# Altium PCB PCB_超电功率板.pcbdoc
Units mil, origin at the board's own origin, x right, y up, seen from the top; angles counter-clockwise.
Board outline 3510 x 2835 mil, 2 copper layers (Top Layer, Bottom Layer); 57 components, 25 nets, 167 pads, 0 vias.
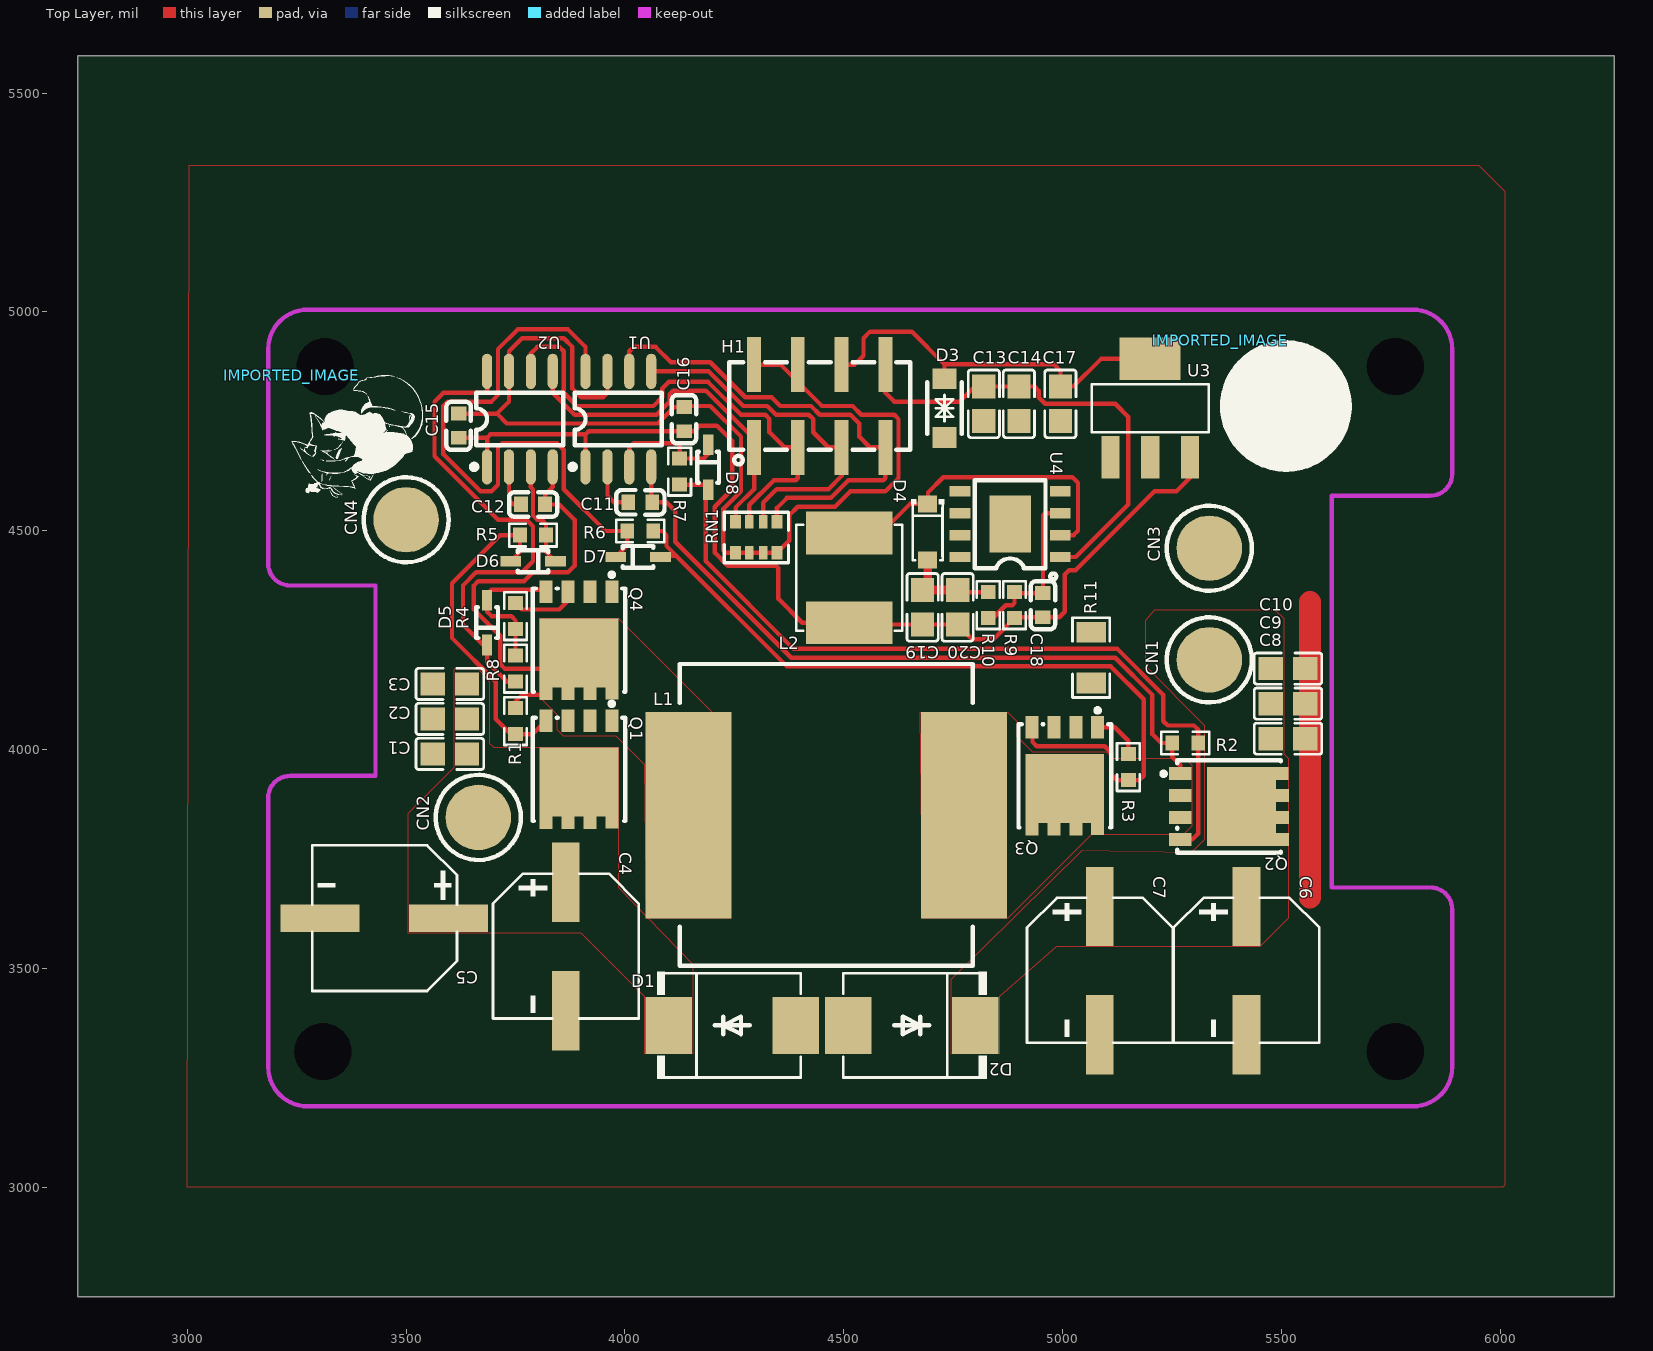
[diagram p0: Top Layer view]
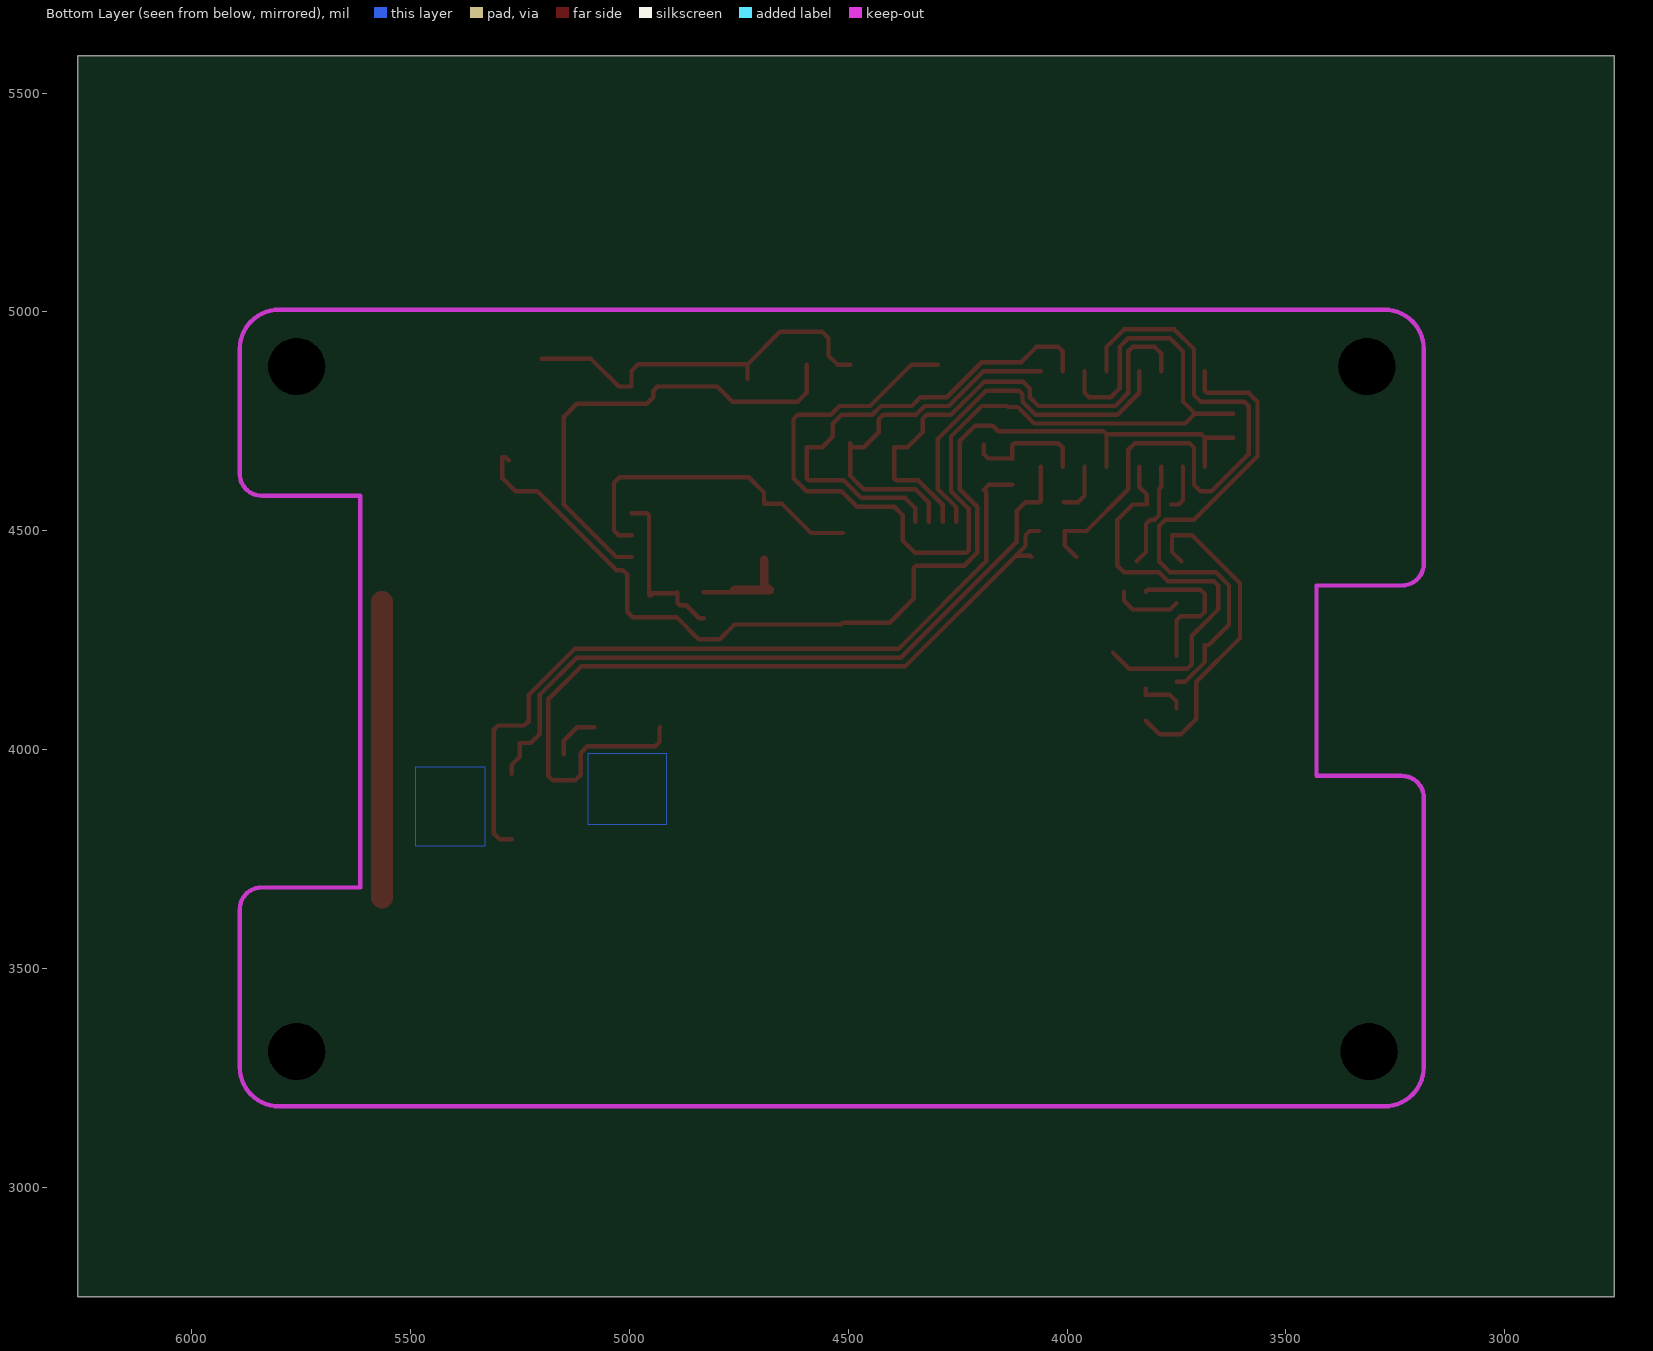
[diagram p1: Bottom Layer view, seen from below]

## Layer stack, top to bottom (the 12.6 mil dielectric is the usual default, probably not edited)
Top Layer: signal copper (thickness not stored)
Dielectric: dielectric 12.6, FR-4, Dk 4.8
Bottom Layer: signal copper (thickness not stored)

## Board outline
6260,2750 2750,2750 2750,5585 6260,5585
cut-out: 3380,4875 ccw(c3315,4875) 3250,4875 ccw(c3315,4875)
cut-out: 3375,3310 ccw(c3310,3310) 3245,3310 ccw(c3310,3310)
cut-out: 5825,3310 ccw(c5760,3310) 5695,3310 ccw(c5760,3310)
cut-out: 5825,4875 ccw(c5760,4875) 5695,4875 ccw(c5760,4875)

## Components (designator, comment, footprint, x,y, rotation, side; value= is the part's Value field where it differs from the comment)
C1 "22u" C0805 3600,3990 r180 top
C2 "22u" C0805 3600,4070 r180 top
C3 "22u" C0805 3600,4150 r180 top
C4 "220uF" CAP-SMD_BD8.0-L8.3-W8.3-LS9.3-FD 3865,3550 r270 top
C5 "220uF" CAP-SMD_BD8.0-L8.3-W8.3-LS9.3-FD 3450,3615 r180 top
C6 "220uF" CAP-SMD_BD8.0-L8.3-W8.3-LS9.3-FD 5420,3495 r270 top
C7 "220uF" CAP-SMD_BD8.0-L8.3-W8.3-LS9.3-FD 5085,3495 r270 top
C8 "22u" C0805 5515,4025 r0 top
C9 "22u" C0805 5515,4105 r0 top
C10 "22u" C0805 5515,4185 r0 top
C11 "100n" C0603 4035,4565 r180 top
C12 "100n" C0603 3790,4560 r180 top
C13 "22u" C0805 4820,4790 r270 top
C14 "22u" C0805 4900,4790 r270 top
C15 "1u" C0603 3620,4740 r90 top
C16 "1u" C0603 4135,4755 r90 top
C17 "22u" C0805 4995,4790 r270 top
C18 "330pF" C0603 4955,4330 r90 top
C19 "22u" C0805 4680,4325 r90 top
C20 "22u" C0805 4760,4325 r90 top
CN1 "m3铜柱" SMT铜柱 5335,4205 r0 top
CN2 "m3铜柱" SMT铜柱 3665.01,3845 r0 top
CN3 "m3铜柱" SMT铜柱 5335,4460 r0 top
CN4 "m3铜柱" SMT铜柱 3500.01,4525 r0 top
D1 "5.0SMDJ30A" SMC_L6.9-W5.9-LS7.9-RD 4245,3370 r0 top
D2 "5.0SMDJ30A" SMC_L6.9-W5.9-LS7.9-RD 4655,3370 r180 top
D3 "SMFJ5.0CA" SOD-123FL_L2.8-W1.8-LS3.7-BI 4730,4780 r90 top
D4 "DSK310_C713648" SOD-123_L2.7-W1.8-LS3.7-RD 4691.5,4497.2 r270 top
D5 "1N4007WS" SOD-323_L1.6-W1.3-LS2.6-RD 3685,4290 r90 top
D6 "1N4007WS" SOD-323_L1.6-W1.3-LS2.6-RD 3790,4430 r180 top
D7 "1N4007WS" SOD-323_L1.6-W1.3-LS2.6-RD 4030,4440 r0 top
D8 "1N4007WS" SOD-323_L1.6-W1.3-LS2.6-RD 4190,4645 r270 top
H1 "MF254VS-12-08P" HDR-SMD_8P-P2.54_MF254VS-12-08P 4445,4785 r0 top
IMPORTED_IMAGE "IMPORTED_IMAGE" IMPORTED_IMAGE 3238.58,4855.24 r0 top
IMPORTED_IMAGE "IMPORTED_IMAGE" IMPORTED_IMAGE 5360.03,4934.98 r0 top
L1 "15uH" IND-SMD_L17.5-W17.0_YXMAC1770 4460,3850 r0 top
L2 "330uH" IND-SMD_L6.0-W6.0_SWPA6045S 4512.2,4392.2 r90 top
Q1 "BSC070N10NS5" PG-TDSON-8_L5.0-W6.0-P1.27-BL-EP 3895.03,3954.97 r180 top
Q2 "BSC070N10NS5" PG-TDSON-8_L5.0-W6.0-P1.27-BL-EP 5380.03,3869.97 r270 top
Q3 "BSC070N10NS5" PG-TDSON-8_L5.0-W6.0-P1.27-BL-EP 5005.03,3939.97 r180 top
Q4 "BSC070N10NS5" PG-TDSON-8_L5.0-W6.0-P1.27-BL-EP 3895.03,4249.97 r180 top
R1 "10k" R0603 3750,4065 r90 top
R2 "10k" R0603 5280,4015 r180 top
R3 "10k" R0603 5150,3960 r90 top
R4 "10k" R0603 3750,4305 r270 top
R5 "4.7" R0603 3790,4490 r180 top
R6 "4.7" R0603 4035,4499.3 r0 top
R7 "4.7" R0603 4125,4635 r270 top
R8 "4.7" R0603 3750,4185 r90 top
R9 "33k" R0603 4890,4330 r90 top
R10 "4.7k" R0603 4830,4330 r90 top
R11 "0" R1206 5065,4210 r90 top
RN1 "10k" RES-ARRAY-SMD_0603-8P-L3.2-W1.6-BL 4300,4485 r180 top
U1 "UCC27211D" SOIC-8_L4.9-W3.9-P1.27-LS6.2-BL 3984.97,4754.99 r0 top
U2 "UCC27211D" SOIC-8_L4.9-W3.9-P1.27-LS6.2-BL 3759.97,4754.99 r0 top
U3 "AMS1117-5.0" SOT-223_L6.5-W3.5-P2.30-LS7.0-BR 5200,4780 r270 top
U4 "XL7005ADJ" ESOP-8_L4.9-W3.9-P1.27-LS6.0-BL-EP 4880,4515 r90 top

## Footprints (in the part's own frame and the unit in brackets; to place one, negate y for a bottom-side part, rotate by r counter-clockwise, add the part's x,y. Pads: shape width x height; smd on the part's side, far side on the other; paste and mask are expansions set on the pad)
C0603 [mm]
  rect 0.8x0.9 smd paste+0 mask+0.051: 1(-0.7,0) 2(0.7,0)
  silkscreen extent -1.41,-0.71 1.39,0.72
C0805 [mm]
  rect 1.41x1.35 smd paste-100 mask+0.051: 1(-1,0) 2(1,0)
  silkscreen extent -1.96,-0.9 1.96,0.9
CAP-SMD_BD8.0-L8.3-W8.3-LS9.3-FD [mm]
  rect 4.6x1.6 smd paste+0 mask+0.051: 1(-3.724,0) 2(3.724,0)
  silkscreen extent -4.23,-4.23 4.18,4.23
ESOP-8_L4.9-W3.9-P1.27-LS6.0-BL-EP [mm]
  rect 0.6x1.2 smd paste+0 mask+0.051: 1(-1.905,-2.908) 2(-0.635,-2.908) 3(0.635,-2.908) 4(1.905,-2.908) 5(1.905,2.908) 6(0.635,2.908) 7(-0.635,2.908) 8(-1.905,2.908)
  rect 3.3x2.4 smd paste+0 mask+0.051: 9(0,0)
  silkscreen extent -3.2,-2.67 2.55,2.05
HDR-SMD_8P-P2.54_MF254VS-12-08P [mm]
  rect 0.8x3.2 smd paste+0 mask+0.051: 1(-3.81,-2.4) 2(-3.81,2.4) 3(-1.27,-2.4) 4(-1.27,2.4) 5(1.27,-2.4) 6(1.27,2.4) 7(3.81,-2.4) 8(3.81,2.4)
  silkscreen extent -5.25,-3.39 5.25,2.54
IMPORTED_IMAGE [mil]
  silkscreen extent 0,-280 300,0
IND-SMD_L6.0-W6.0_SWPA6045S [mm]
  rect 2.474x5.02 smd paste+0 mask+0.051: 1(-2.603,0) 2(2.603,0)
  silkscreen extent -3.08,-3.08 3.08,3.08
IND-SMD_L17.5-W17.0_YXMAC1770 [mm]
  rect 5x12 smd paste+0 mask+0.051: 1(-8,0) 2(8,0)
  silkscreen extent -8.5,-8.73 8.5,8.78
PG-TDSON-8_L5.0-W6.0-P1.27-BL-EP [mil]
  rect 29.5x51.2 smd paste-3937.01 mask+2: 1(-75,-111) 2(-25,-111) 3(25,-111) 4(75,-111) 5(75,111) 6(25,111) 7(-25,111) 8(-75,110)
  rect 179.53x157.48 smd paste-3937.01 mask+2: 9(0,29)
  silkscreen extent -106,-154 106,118
R0603 [mil]
  rect 31.75x34.02 smd paste-3937.01 mask+2: 1(-29.66,0) 2(29.66,0)
  silkscreen extent -55,-26 55,26
R1206 [mil]
  rect 47.54x66.97 smd paste-3937.01 mask+2: 1(-58.22,0) 2(58.22,0)
  silkscreen extent -91,-42 91,42
RES-ARRAY-SMD_0603-8P-L3.2-W1.6-BL [mm]
  rect 0.65x0.8 smd paste+0 mask+0.051: 1(-1.2,-0.9) 4(1.2,-0.9) 5(1.2,0.9) 8(-1.2,0.9)
  rect 0.5x0.8 smd paste+0 mask+0.051: 2(-0.4,-0.9) 3(0.4,-0.9) 6(0.4,0.9) 7(-0.4,0.9)
  silkscreen extent -1.87,-1.45 1.87,1.47
SMC_L6.9-W5.9-LS7.9-RD [mm]
  rect 2.7x3.3 smd paste+0 mask+0.051: 1(-3.686,0) 2(3.686,0)
  silkscreen extent -4.36,-3.1 3.98,3.1
SMT铜柱 [mm]
  round 3.8 smd paste+0 mask+0.051: 1(0,0)
  silkscreen extent -2.47,-2.47 2.47,2.47
SOD-123_L2.7-W1.8-LS3.7-RD [mm]
  rect 1x1.1 smd paste+0 mask+0.051: 1(-1.627,0) 2(1.627,0)
  silkscreen extent -1.9,-0.94 1.65,0.95
SOD-123FL_L2.8-W1.8-LS3.7-BI [mm]
  rect 1.2x1.4 smd paste+0 mask+0.051: 1(-1.7,0) 2(1.7,0)
  silkscreen extent -1.5,-1 1.5,1
SOD-323_L1.6-W1.3-LS2.6-RD [mm]
  rect 1.2x0.6 smd paste+0 mask+0.05: 1(-1.3,0) 2(1.3,0)
  silkscreen extent -0.89,-0.64 0.89,0.64
SOIC-8_L4.9-W3.9-P1.27-LS6.2-BL [mm]
  oval 0.588x2.045 smd paste+0 mask+0.051: 1(-1.905,-2.772) 2(-0.635,-2.772) 3(0.635,-2.772) 4(1.905,-2.772) 5(1.905,2.772) 6(0.635,2.772) 7(-0.635,2.772) 8(-1.905,2.772)
  silkscreen extent -2.8,-2.92 2.53,1.52
SOT-223_L6.5-W3.5-P2.30-LS7.0-BR [mm]
  rect 2.465x1.05 smd paste+0 mask+0.051: 1(2.858,-2.3) 2(2.857,0) 3(2.857,2.3)
  rect 2.465x3.54 smd paste+0 mask+0.051: 4(-2.857,0)
  silkscreen extent -1.4,-3.4 1.4,3.4

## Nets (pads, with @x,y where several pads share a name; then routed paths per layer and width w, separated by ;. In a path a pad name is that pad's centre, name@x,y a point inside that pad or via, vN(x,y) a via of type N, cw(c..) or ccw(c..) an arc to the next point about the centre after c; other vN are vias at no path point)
10V: C15.1 C16.1 C18.1 C19.1 C20.1 L2.1 R9.1 U1.1 U2.1 U3.3 | length 2538.7
  Top Layer w10: C15.1 3685,4712.4 ; U2.1 3685,4712.4 ; U1.1 3910,4719.6 3910,4720 ; L2.1 4516.3,4285.63 C19.1 C20.1 4793.43,4252.2 4841.85,4252.2 R9.1 4892.09,4302.44 C18.1 ; L2.1@4512.2,4290 4405,4290 4350,4345 4350,4415 4345,4420 4235,4420 4205,4450 4205,4555 4245,4595 4245,4705 4210,4740 4170,4740 4157.4,4727.4 C16.1 3917.4,4727.4 3910,4720 ; C18.1 4992.4,4302.4 5005,4315 5005,4400 5015,4410 5030,4410 5210,4590 5260,4590 5290.55,4620.55 U3.3 5282.5,4667.5 U3.3@5275.6,4660.6 ; 3685,4712.4 3692.6,4720 3910,4720
$1N34: D5.2 Q4.4 R4.2 R8.2 | length 334.4
  Top Layer w10: R8.2 R4.2 ; R4.2 3750,4295 3740,4305 3695,4305 3685,4315 D5.2 3685,4355 3695,4365 3816,4365 Q4.4
$1N35: D6.2 Q1.4 R1.1 R5.2 | length 763.3
  Top Layer w10: D6.2 3760.34,4451.52 R5.2 ; R1.1 3739.7,4035.3 3705,4070 3705,4155 3605,4255 3605,4380 3715,4490 R5.2 ; R1.1 3789.34,4035.34 Q1.4
$1N36: D8.2 Q2.4 R2.1 R7.2 | length 1838.1
  Top Layer w10: R7.2 4178.48,4605.34 D8.2 4185,4588.8 4185,4430 4385,4230 5125,4230 5230,4125 5230,4065 5240,4055 5300,4055 5309.7,4045.3 R2.1 ; Q2.4 5296.6,3795 5309.66,3808.06 R2.1
$1N40: D7.2 Q3.4 R3.1 R6.2 | length 1863.9
  Top Layer w10: R6.2 4085.7,4499.3 4095,4490 4095,4465 4117.44,4442.56 ; D7.2 4083.74,4442.56 4117.44,4442.56 ; Q3.4 4931,4049.99 4931,4017.37 4941,4007.37 5096,4007.37 5111,3992.37 5111,3942.31 5122.97,3930.34 R3.1 ; R3.1 5175.3,3930.3 5185,3940 5185,4115 5110,4190 4370,4190 4117.44,4442.56
$1N92: C11.2 U1.2 | length 119.5
  Top Layer w10: U1.2 3960,4580 3975,4565 C11.2
$1N105: D5.1 R8.1 U2.8 | length 1139.9
  Top Layer w10: U2.8@3685,4864.2 3685,4820 3680,4815 3585.2,4815 3565,4794.8 3565,4670 3710,4525 3775,4525 3790,4510 3790,4430 3765,4405 3660,4405 3630,4375 3630,4285 3676.2,4238.8 D5.1 3685,4200 3729.7,4155.3 R8.1
$1N120: D6.1 R5.1 U2.3 | length 244.9
  Top Layer w10: U2.3 3785,4600 3790,4595 3790,4535 3800,4525 3810,4525 3819.66,4515.34 R5.1 3819.66,4451.52 D6.1
$1N161: D8.1 R7.1 U1.3 | length 286
  Top Layer w10: U1.3 4010,4690 4020,4700 4120,4700 4125,4695 R7.1 4180,4665 4190,4675 D8.1
$1N172: D7.1 R6.1 U1.8 | length 1398.5
  Top Layer w10: U1.8@3910,4864.15 3910,4920 3870,4960 3755,4960 3710,4915 3710,4810 3695,4795 3595,4795 3585,4785 3585,4675 3670,4590 3695,4590 3710,4605 3710,4690 3720,4700 3845,4700 3860,4685 3860,4595 3955.7,4499.3 R6.1 4005.34,4466.52 D7.1
$1N280: C18.2 R9.2 R10.1 U4.3 | length 394
  Top Layer w10: R10.1@4830,4300 4840,4300 4870,4330 4885,4330 4890,4335 R9.2 4892.1,4357.56 C18.2 ; C18.2@4950,4352.56 4955,4352.56 C18.2 ; U4.3 4960,4540 4955,4535 C18.2
$1N391: D4.1 L2.2 U4.2 | length 749.4
  Top Layer w10: L2.2 4584.68,4494.68 4651.25,4561.25 D4.1@4691.53,4561.25 ; D4.1 4692.2,4587.2 4727.2,4622.2 5022.2,4622.2 5035,4609.4 5035,4500 5025,4490 U4.2
$1N753: C12.2 U2.2 | length 107.4
  Top Layer w10: U2.2@3735,4645.85 3735,4570 3745,4560 C12.2
+5V: C17.1 D3.2 H1.6 U3.4 | length 891.9
  Top Layer w10: H1.6 4524.5,4879.5 4545,4900 4545,4940 4560,4955 4655,4955 4730,4880 D3.2 ; 4730,4880.09 4980,4880.09 4995,4865 C17.1 ; C17.1 5024.37,4829.37 5087.5,4892.5 U3.4
GND: C1.2 C2.2 C3.2 C4.2 C5.2 C6.2 C7.2 C8.2 C9.2 C10.2 C13.2 C14.2 C15.2 C16.2 C17.2 C19.2 C20.2 CN3.1 CN4.1 D1.2 D2.2 D3.1 D4.2 H1.2 H1.4 Q3.1 Q3.2 Q3.3 Q4.1 Q4.2 Q4.3 R3.2 R4.1 R10.2 R11.1 R11.2 RN1.5 RN1.6 RN1.7 RN1.8 U1.7 U2.7 U3.1 U4.5 U4.6 U4.7 U4.8 U4.9 | length 3724.8
  Top Layer w10: C15.2 3707.56,4767.56 3735,4795 3735,4864.15 3735,4910 3765,4940 3860,4940 3880,4920 3880,4825 3900,4805 3950,4805 3960,4815 U1.7@3960,4864.2 ; 3707.6,4767.6 3730.2,4745 4075,4745 4112.6,4782.6 C16.2 4137.4,4785 4195,4785 4265,4715 4265,4590 4225,4550 4225,4455 4230.4,4449.6 RN1.5 ; R4.1 3764.66,4320 3850,4320 3870.03,4340.03 Q4.3 ; RN1.5 RN1.6 RN1.7 RN1.8 ; H1.2 4355.5,4879.5 4450,4785 4520,4785 4540,4765 4615,4765 4625,4755 4625,4620 4595,4590 4515,4590 4480,4555 4395,4555 4375,4535 4375,4477.3 RN1.8 ; C20.2 4764.71,4359.66 R10.2 ; Q3.1 5118.97,4051 5149.97,4020 R3.2
  Top Layer w20: D4.2@4691.53,4433.15 4691.53,4375.9 C19.2 C20.2
  Top Layer w50: 5565,3662.5 5565,4337.5
HRTIM1_CHA1: H1.7 RN1.1 U1.6 | length 1136.8
  Top Layer w10: U1.6@4010,4864.2 4010,4910 4020,4920 4070,4920 4105,4885 4195,4885 4275,4805 4335,4805 4355,4785 4425,4785 4445,4765 4515,4765 4535,4745 4535,4715 4559.5,4690.5 H1.7 ; RN1.1 4347.2,4552.2 4370,4575 4470,4575 4510,4615 4590,4615 4595,4620 H1.7 ; H1.7 4589.5,4690.5 H1.7
HRTIM1_CHA2: H1.5 RN1.2 U1.5 | length 847.8
  Top Layer w10: U1.5@4060,4864.2 4190.8,4864.2 4270,4785 4325,4785 4345,4765 4420,4765 4430,4755 4430,4725 4464.5,4690.5 H1.5 ; RN1.2 4315.8,4564.3 4346.5,4595 4465,4595 4495,4625 H1.5 ; H1.5@4495,4700 H1.5
HRTIM1_CHB1: H1.3 RN1.3 U2.6 | length 1128.2
  Top Layer w10: U2.6@3785,4864.2 3785,4905 3800,4920 3850,4920 3860,4910 3860,4815 3890,4785 4065,4785 4085,4805 4085,4825 4100,4840 4190,4840 4265,4765 4320.5,4765 4330,4755.5 4330,4725 4364.5,4690.5 H1.3 4395,4620 4390,4615 4340,4615 4284.2,4559.3 RN1.3
HRTIM1_CHB2: H1.1 RN1.4 U2.5 | length 830.3
  Top Layer w10: U2.5@3835,4864.2 3835,4815 3885,4765 4072.32,4765 4101.79,4794.47 4101.79,4811.78 4110,4820 4185,4820 4295,4710 H1.1 ; RN1.4 4252.8,4552.8 4295,4595 H1.1 ; H1.1@4295,4705.3 H1.1
SW1: C11.1 L1.2 Q2.1 Q2.2 Q2.3 Q3.5 Q3.6 Q3.7 Q3.8 R2.2 U1.4 | length 1673.1
  Top Layer w10: C11.1@4060,4568.14 4062.56,4565.58 C11.1 4060,4567.56 U1.4 ; C11.1 4095,4565 4115,4545 4115,4475 4380,4210 5120,4210 5205,4125 5205,4035 5225,4015 R2.2 ; R2.2 5250.35,3983.32 5269,3964.66 Q2.1
SW2: C12.1 L1.1 Q1.1 Q1.2 Q1.3 Q4.5 Q4.6 Q4.7 Q4.8 R1.2 U2.4 | length 1038.1
  Top Layer w10: R1.2 3750,4110 3765,4125 3820,4125 Q4.5 ; C12.1 3817.56,4582.56 3835,4600 U2.4@3835,4645.85 ; C12.1 3850,4560 3885,4525 3885,4420 3870,4405 3790,4405 3770,4385 3665,4385 3655,4375 3655,4320 3685,4290 3715,4260 3715,4195 3725,4185 3859.1,4185 3895,4221
VCC: C6.1 C7.1 C8.1 C9.1 C10.1 CN1.1 D2.1 Q2.5 Q2.6 Q2.7 Q2.8
VCC1: C13.1 C14.1 H1.8 U4.1 | length 1085
  Top Layer w10: H1.8 4595,4815 4615,4795 4765,4795 4799.37,4829.37 C13.1 C14.1 4935,4830 4945,4820 4945,4805 4960,4790 5120,4790 5150,4760 5150,4560 5030,4440 U4.1
VCUP: C1.1 C2.1 C3.1 C4.1 C5.1 CN2.1 D1.1 Q1.5 Q1.6 Q1.7 Q1.8
"": Q1.9 Q2.9 Q3.9 Q4.9 U3.2 U4.4

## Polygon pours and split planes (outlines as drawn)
SW1 on Bottom Layer (solid, remove dead copper, pour order 0): 4914.97,3990 5094.97,3990 5094.97,3830 4914.97,3830
VCC on Bottom Layer (solid, remove dead copper, pour order 1): 5329,3780 5329,3960 5489,3960 5489,3780
VCC on Top Layer (solid, remove dead copper, pour order 2): 5210,4320 5485,4320 5505,4300 5505,3990 5515,3980 5515,3770 5515,3640 5515,3615 5450,3550 5405,3550 4985,3550 4855,3435 4855,3305 4745,3305 4745,3475 5045,3770 5295,3765 5325,3795 5325,4055 5190,4190 5190,4295
SW1 on Top Layer (solid, remove dead copper, pour order 3): 4675,4085 4875,4085 4895,4065 4895,4030 4930,3995 4960,3995 5100,3995 5115,3980 5280,3980 5295,3965 5295,3825 5275,3805 5065,3805 4875,3615 4680,3615
SW2 on Top Layer (solid, remove dead copper, pour order 4): 3805,4300 3985,4300 4200,4085 4240,4085 4240,3615 4050,3615 4045,3965 3980,4030 3860,4030 3845,4045 3845,4080 3805,4120
VCUP on Top Layer (solid, remove dead copper, pour order 5): 3610,4185 3665,4185 3690,4155 3690,4015 3700,4005 3805,4005 3985,4005 3985,3820 3985,3685 4155,3510 4155,3305 4045,3305 4045,3435 3900,3580 3505,3580 3505,3855 3610,3960 3610,4045
GND on Top Layer (solid, remove dead copper, pour order 6): 3005,5335 5950,5335 6010,5275 6010,3005 6005,3000 3000,3000

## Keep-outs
Board Outline Layer:
  lines w10 net "": 5835,3685 5615,3685 5615,4580 5835,4580 ; 5840,3685 cw(c5840,3635) 5890,3635 5890,3275 cw(c5800,3275) 5800,3185 3275,3185 cw(c3275,3275) 3185,3275 3185,3890 cw(c3235,3890) 3235,3940 3430,3940 3430,4375 3235,4375 cw(c3235,4425) 3185,4425 3185,4915 cw(c3275,4915) 3275,5005 5800,5005 cw(c5800,4915) 5890,4915 5890,4630 cw(c5840,4630) 5840,4580

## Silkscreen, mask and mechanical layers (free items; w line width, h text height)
Top Solder Mask Layer:
  lines w54 net "": 5565,3669.28 5565,4370 ; 5565,3662.5 5565,4337.5 5565,3662.5
Mechanical Layer:
  circle w1 net "": c3315,4875 r65
  circle w1 net "": c3310,3310 r65
  circle w1 net "": c5760,3310 r65
  circle w1 net "": c5760,4875 r65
